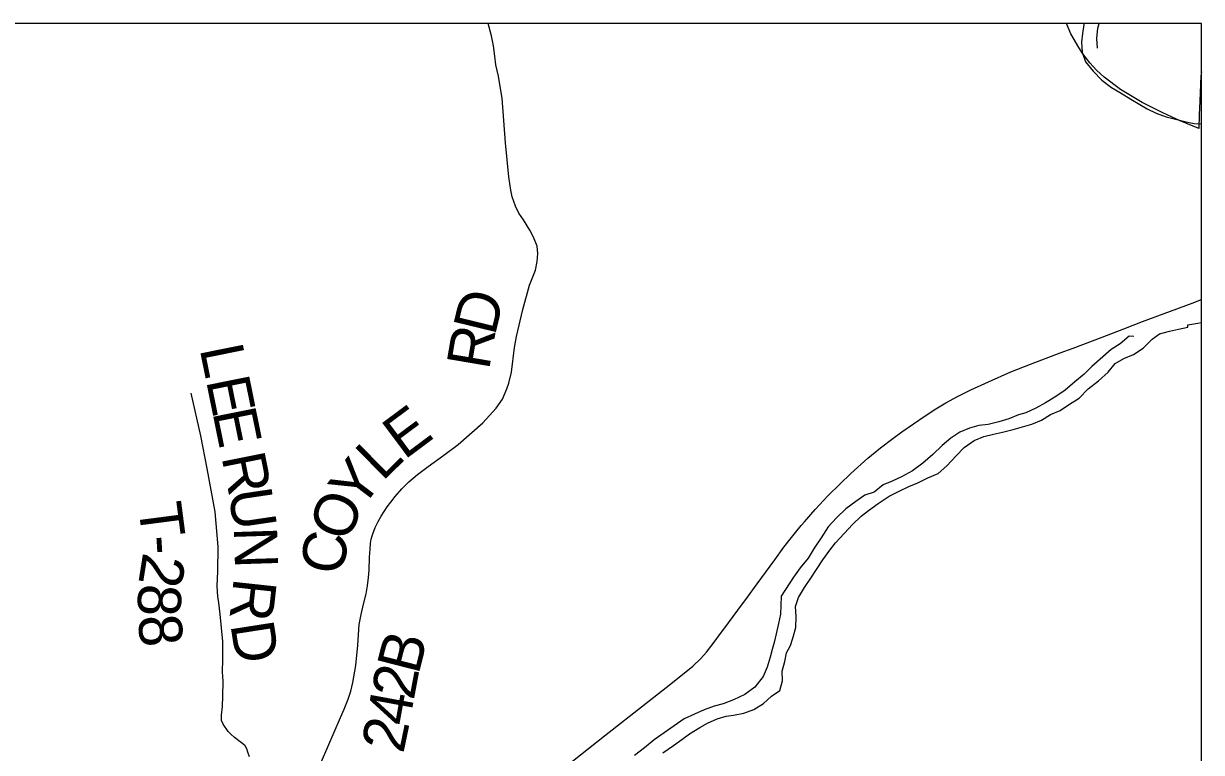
# Model space of a CAD drawing. Extents: x -10.5 to 40.6, y -3.2 to 22.
# Drawn here: x -5.292 to -3.744, y 19.942 to 20.9 of the extents above; entities that cross this region are included whole.
import ezdxf

# ---------------------------------------------------------------- set-up
doc = ezdxf.new("R2010")
doc.units = 0
for name, color, linetype in [('GM_X_Major_River', 7, 'Continuous'), ('GM_X_State_Route', 7, 'Continuous'), ('GM_X_Township_Road', 7, 'Continuous'), ('GM_X_Township_Road_Text', 7, 'Continuous'), ('GM_X_Township_Text', 7, 'Continuous')]:
    doc.layers.add(name, color=color, linetype=linetype)

msp = doc.modelspace()

# ---------------------------------------------------------------- linework, layer by layer
at = {"layer": 'GM_X_Major_River'}
for points in [[(-3.8988, 20.9), (-3.899, 20.8989), (-3.9008, 20.8868), (-3.9022, 20.8754), (-3.9013, 20.8625), (-3.897, 20.8496), (-3.8866, 20.8372), (-3.8752, 20.8256), (-3.8626, 20.8159), (-3.85, 20.8084), (-3.8374, 20.8006), (-3.8256, 20.7935), (-3.8157, 20.7879), (-3.8039, 20.7823), (-3.791, 20.7772), (-3.7785, 20.7743), (-3.7667, 20.7714)], [(-3.8809, 20.8676), (-3.8818, 20.8805), (-3.8804, 20.8938), (-3.8788, 20.9)], [(-3.7667, 20.7714), (-3.7542, 20.7688), (-3.7445, 20.7682)], [(-4.4521, 19.9412), (-4.4382, 19.9508), (-4.4269, 19.9589), (-4.4168, 19.9662), (-4.4036, 19.9747), (-4.3935, 19.9805), (-4.3807, 19.9859), (-4.369, 19.9895), (-4.3592, 19.9907), (-4.3456, 19.9935), (-4.3324, 19.9982), (-4.3196, 20.0063), (-4.3091, 20.0159), (-4.2982, 20.0232), (-4.2949, 20.0361), (-4.2951, 20.0486), (-4.2918, 20.0612), (-4.2897, 20.0726), (-4.2845, 20.0825), (-4.2812, 20.092), (-4.2775, 20.1061), (-4.2769, 20.1205), (-4.2778, 20.1338), (-4.2738, 20.1456), (-4.266, 20.1586), (-4.2574, 20.1708), (-4.25, 20.1822), (-4.2418, 20.1952), (-4.2325, 20.2078), (-4.2254, 20.2174), (-4.2134, 20.23), (-4.203, 20.2415), (-4.1917, 20.2523), (-4.182, 20.2599), (-4.1692, 20.2692), (-4.1549, 20.2788), (-4.1417, 20.2854), (-4.1289, 20.2912), (-4.1169, 20.2963), (-4.1037, 20.3029), (-4.0905, 20.3087), (-4.0789, 20.3187), (-4.0669, 20.3317), (-4.0561, 20.3428), (-4.0429, 20.3517), (-4.0305, 20.3571), (-4.0177, 20.3603), (-4.006, 20.363), (-3.9916, 20.3662), (-3.9675, 20.3733), (-3.9547, 20.3788), (-3.9426, 20.3861), (-3.9302, 20.3915), (-3.9178, 20.3996), (-3.905, 20.4077), (-3.8931, 20.4196), (-3.8796, 20.4304), (-3.8672, 20.4419), (-3.8579, 20.4533), (-3.8466, 20.4595), (-3.8338, 20.465), (-3.821, 20.4734), (-3.8094, 20.4853), (-3.7996, 20.4922), (-3.7864, 20.4958), (-3.7747, 20.4982), (-3.7622, 20.501), (-3.7623, 20.504)], [(-3.7623, 20.504), (-3.7491, 20.506), (-3.7445, 20.5069)], [(-3.8333, 20.4885), (-3.8393, 20.4892), (-3.8513, 20.4788), (-3.863, 20.4715), (-3.8885, 20.4492), (-3.8986, 20.4389), (-3.9106, 20.4289), (-3.9237, 20.4181), (-3.9372, 20.4089), (-3.9493, 20.4016), (-3.962, 20.3942), (-3.9752, 20.3884), (-3.985, 20.3856), (-3.9975, 20.3802), (-4.0107, 20.3766), (-4.0246, 20.3731), (-4.0371, 20.3714), (-4.0492, 20.3683), (-4.062, 20.3628), (-4.0736, 20.3548), (-4.0853, 20.3451), (-4.0972, 20.3336), (-4.1104, 20.3221), (-4.1239, 20.3121), (-4.1385, 20.304), (-4.1506, 20.2982), (-4.1626, 20.2935), (-4.1743, 20.2839), (-4.1867, 20.28), (-4.1987, 20.2719), (-4.2115, 20.2619), (-4.2239, 20.25), (-4.2347, 20.2382), (-4.244, 20.224), (-4.2533, 20.2103), (-4.2611, 20.1973), (-4.2716, 20.1847), (-4.2802, 20.1724), (-4.2965, 20.1472), (-4.2972, 20.1351), (-4.2974, 20.1237), (-4.3003, 20.1112), (-4.3032, 20.0979), (-4.3057, 20.0865), (-4.3086, 20.077), (-4.3112, 20.0671), (-4.3148, 20.0538), (-4.3204, 20.0416), (-4.3312, 20.0278), (-4.3443, 20.0178), (-4.359, 20.0108), (-4.3726, 20.0057), (-4.3846, 20.0026), (-4.3978, 19.9979), (-4.4106, 19.9921), (-4.4238, 19.9859), (-4.437, 19.977), (-4.4505, 19.9674), (-4.4636, 19.9585), (-4.476, 19.9478), (-4.4891, 19.9378)]]:
    msp.add_lwpolyline(points, dxfattribs=at)
at = {"layer": 'GM_X_State_Route'}
for points in [[(-3.7478, 20.762), (-3.7725, 20.7719), (-3.7952, 20.7825), (-3.8222, 20.7961), (-3.851, 20.8134), (-3.8723, 20.8296), (-3.8822, 20.8387), (-3.8911, 20.8482), (-3.9002, 20.8602), (-3.9057, 20.8685), (-3.9159, 20.8863), (-3.9218, 20.9)], [(-3.7445, 20.8366), (-3.7451, 20.8313), (-3.7464, 20.798), (-3.7474, 20.78), (-3.7478, 20.762)], [(-4.2776, 20.231), (-4.2704, 20.24), (-4.266, 20.245), (-4.2519, 20.2613), (-4.2349, 20.2795), (-4.2197, 20.2945), (-4.2052, 20.3087), (-4.1826, 20.3286), (-4.166, 20.3424), (-4.1501, 20.3546), (-4.1379, 20.3633), (-4.1229, 20.3738), (-4.1075, 20.3843), (-4.0936, 20.3935), (-4.0803, 20.4015), (-4.0648, 20.4096), (-4.0475, 20.4183), (-4.0244, 20.4292), (-3.995, 20.4422), (-3.9689, 20.4523), (-3.9299, 20.4673), (-3.913, 20.4734), (-3.8749, 20.4877), (-3.8466, 20.4985), (-3.8218, 20.5081), (-3.7567, 20.5326), (-3.7445, 20.5372)], [(-4.3721, 20.1037), (-4.3535, 20.1289), (-4.3408, 20.1459), (-4.328, 20.1635), (-4.3048, 20.1951), (-4.2931, 20.2115), (-4.283, 20.2242), (-4.2776, 20.231)], [(-4.5814, 19.9221), (-4.5285, 19.9635), (-4.4741, 20.0064), (-4.4416, 20.0318), (-4.4126, 20.0551), (-4.4019, 20.0652), (-4.3945, 20.0738), (-4.3833, 20.0884), (-4.3774, 20.0966), (-4.3721, 20.1037)]]:
    msp.add_lwpolyline(points, dxfattribs=at)
at = {"layer": 'GM_X_Township_Road'}
for points in [[(-4.9005, 19.9298), (-4.892, 19.9492), (-4.8754, 19.9877), (-4.8705, 19.9987), (-4.8654, 20.0118), (-4.862, 20.0225), (-4.8591, 20.0336), (-4.8555, 20.056), (-4.8526, 20.0829), (-4.8508, 20.1102), (-4.8484, 20.1233), (-4.8451, 20.1368), (-4.8419, 20.1504), (-4.8399, 20.161), (-4.8386, 20.1718), (-4.8379, 20.1815), (-4.8375, 20.1985), (-4.8367, 20.2089), (-4.836, 20.2167), (-4.835, 20.2222), (-4.8336, 20.2279), (-4.8298, 20.2375), (-4.826, 20.2453), (-4.822, 20.2524), (-4.814, 20.2645), (-4.8095, 20.2708), (-4.8038, 20.2781), (-4.7951, 20.2882), (-4.7857, 20.2975), (-4.7742, 20.3072), (-4.7602, 20.3179), (-4.7396, 20.3328), (-4.7208, 20.3466), (-4.6885, 20.375), (-4.6711, 20.3943), (-4.6627, 20.4064), (-4.6569, 20.4198), (-4.6543, 20.4272), (-4.6509, 20.4416), (-4.6467, 20.4741), (-4.6441, 20.4884), (-4.6361, 20.5239), (-4.6273, 20.5559), (-4.6195, 20.5757), (-4.6172, 20.5871), (-4.6163, 20.5977), (-4.6173, 20.6072), (-4.6218, 20.619), (-4.6267, 20.6282), (-4.6351, 20.642), (-4.6411, 20.6506), (-4.6457, 20.66), (-4.6499, 20.6721), (-4.6517, 20.6808), (-4.6545, 20.6987), (-4.6588, 20.7434), (-4.661, 20.7724), (-4.6633, 20.8019), (-4.6662, 20.8198), (-4.6681, 20.8308), (-4.6713, 20.8457), (-4.6726, 20.8572), (-4.6744, 20.8706), (-4.6773, 20.8838), (-4.6814, 20.9)], [(-4.9952, 19.9362), (-4.997, 19.942), (-4.9986, 19.9465), (-5.0008, 19.9507), (-5.0036, 19.9533), (-5.0071, 19.9559), (-5.0149, 19.9615), (-5.0195, 19.9657), (-5.023, 19.9694), (-5.0295, 19.9789), (-5.0316, 19.9838), (-5.0318, 19.9907), (-5.0307, 20.0022), (-5.0299, 20.0159), (-5.0298, 20.0357), (-5.0303, 20.0478), (-5.03, 20.0638), (-5.03, 20.0877), (-5.0335, 20.1234), (-5.0352, 20.1386), (-5.0365, 20.147), (-5.0375, 20.1606), (-5.0364, 20.1799), (-5.036, 20.2122), (-5.0402, 20.2581), (-5.0507, 20.3149), (-5.059, 20.3581), (-5.0717, 20.4141)]]:
    msp.add_lwpolyline(points, dxfattribs=at)
at = {"layer": 'GM_X_Township_Text'}
msp.add_lwpolyline([(-3.7445, 16.8499), (-3.7445, 20.9), (-6.1618, 20.9)], dxfattribs=at)

# ---------------------------------------------------------------- texts
at = {"layer": 'GM_X_Township_Road_Text'}
for s, rotation, p in [('D', 76.3154, (-4.6728, 20.4884)), ('R', 80.3375, (-4.6804, 20.4434)), ('L', 281.4326, (-5.0606, 20.4725)), ('E', 281.4324, (-5.0522, 20.4308)), ('E', 281.4324, (-5.0438, 20.3892)), ('E', 36.7439, (-4.7916, 20.3258)), ('R', 281.3023, (-5.0319, 20.3304)), ('Y', 52.8992, (-4.8491, 20.2591)), ('L', 44.5757, (-4.8204, 20.2973)), ('U', 278.4676, (-5.0229, 20.2854)), ('T', 277.4264, (-5.1415, 20.267)), ('O', 67.6351, (-4.8662, 20.2162)), ('-', 273.4916, (-5.1361, 20.2259)), ('N', 271.8436, (-5.0157, 20.2377)), ('C', 80.555, (-4.8729, 20.1734)), ('2', 260.9278, (-5.1345, 20.2059)), ('R', 263.8175, (-5.0155, 20.1723)), ('8', 267.5386, (-5.1407, 20.1642)), ('8', 275.6213, (-5.142, 20.1205)), ('D', 278.8489, (-5.0202, 20.11)), ('B', 75.6551, (-4.7732, 20.0428)), ('2', 79.38, (-4.7794, 20.0094)), ('4', 79.6127, (-4.7857, 19.975)), ('2', 78.2295, (-4.7931, 19.9393))]:
    msp.add_text(s, height=0.0568, rotation=rotation, dxfattribs=at).set_placement(p)

doc.saveas('drawing.dxf')
